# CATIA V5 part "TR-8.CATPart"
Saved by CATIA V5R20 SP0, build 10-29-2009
Part number: _TR-8
Definition: NONE
Nomenclature: _TR-8
Source: Unknown
Description: PART-_TR-8-DESC
Bounding box of the stored display mesh (mm): x 0 to 9, y -4.9 to 4.9, z -4.9 to 4.9
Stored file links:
  C:\Users\Utente\Desktop\IO LAVORO\3D X SITO CF\X SITO\PLASTICA\TR\TR-8.CATPart
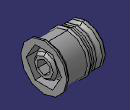
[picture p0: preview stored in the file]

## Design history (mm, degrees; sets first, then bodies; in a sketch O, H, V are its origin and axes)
Body1 "_TR-8" (main body)
  Solid1: solid without history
